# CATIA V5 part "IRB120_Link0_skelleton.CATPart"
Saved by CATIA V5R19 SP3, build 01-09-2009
Part number: IRB120_Link0_skelleton
Bounding box of the stored display mesh (mm): x 0 to 0, y 0 to 0, z 0 to 100
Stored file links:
  Z:\Projects\ABB_Robotics\ABB LIB\V5\V5PARTS\ABB\120\IRB120_Link0_skelleton.CATPart
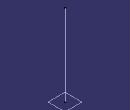
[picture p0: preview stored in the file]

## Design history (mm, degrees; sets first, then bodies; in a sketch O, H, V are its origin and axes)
Body1 (main body)
  Line1: type PtPt, FirstPoint {point type Coord, X 0, Y 0, Z 0}, SecondPoint {point type Coord, X 0, Y 0, Z 100, RefPoint {point type Coord, X 0, Y 0, Z 0}}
